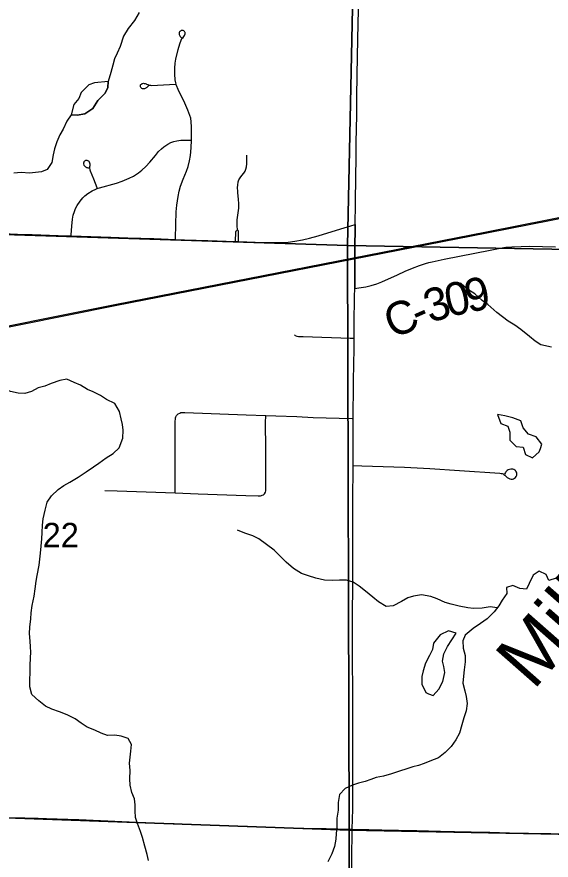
# Model space of a CAD drawing. Extents: x 0 to 34, y 0 to 22.
# Drawn here: x 4.092 to 5.012, y 18.428 to 19.878 of the extents above; entities that cross this region are included whole.
import ezdxf

# ---------------------------------------------------------------- set-up
doc = ezdxf.new("R2010")
doc.units = 0
for name, color, linetype in [('GM_X_County_Road', 7, 'Continuous'), ('GM_X_County_Road_Text', 7, 'Continuous'), ('GM_X_Minor_Lake', 7, 'Continuous'), ('GM_X_Minor_River', 7, 'Continuous'), ('GM_X_Minor_River_Text', 7, 'Continuous'), ('GM_X_Rail_Line', 7, 'Continuous'), ('GM_X_Section', 7, 'Continuous'), ('GM_X_Section_Text', 7, 'Continuous'), ('GM_X_State_Route', 7, 'Continuous'), ('GM_X_Township_Road', 7, 'Continuous')]:
    doc.layers.add(name, color=color, linetype=linetype)

msp = doc.modelspace()

# ---------------------------------------------------------------- linework, layer by layer
at = {"layer": 'GM_X_County_Road'}
for points in [[(4.3666, 19.7624), (4.3659, 19.7649), (4.365, 19.7698), (4.3643, 19.7797), (4.3642, 19.7896), (4.3647, 19.7983), (4.3658, 19.8051), (4.3698, 19.822), (4.3727, 19.8315), (4.3751, 19.8379), (4.3766, 19.8406), (4.3785, 19.8428), (4.3797, 19.8444), (4.3809, 19.8459), (4.3815, 19.8469), (4.3817, 19.8476), (4.382, 19.8485), (4.3821, 19.8494), (4.3821, 19.8501), (4.3819, 19.8512), (4.3817, 19.852), (4.3811, 19.8529), (4.3804, 19.8537), (4.3798, 19.8542), (4.3789, 19.8546), (4.378, 19.8548), (4.3772, 19.8549), (4.3762, 19.8548), (4.3753, 19.8545), (4.3745, 19.854), (4.3738, 19.8535), (4.373, 19.8528), (4.3724, 19.8521), (4.372, 19.8513), (4.3717, 19.8505), (4.3716, 19.8495), (4.3716, 19.8486), (4.3718, 19.8476), (4.3721, 19.8466), (4.3728, 19.8453), (4.3736, 19.8443), (4.3745, 19.8434), (4.3754, 19.8426), (4.3766, 19.8419)], [(4.3199, 19.7606), (4.3194, 19.7599), (4.3186, 19.7589), (4.3177, 19.7581), (4.3168, 19.7573), (4.3161, 19.7566), (4.3152, 19.7559), (4.3144, 19.7554), (4.3135, 19.7549), (4.3122, 19.7544), (4.3112, 19.7542), (4.3102, 19.7542), (4.3093, 19.7542), (4.3084, 19.7545), (4.3076, 19.7548), (4.3067, 19.7554), (4.3061, 19.7559), (4.3056, 19.7567), (4.3052, 19.7575), (4.3051, 19.7584), (4.305, 19.7593), (4.3052, 19.7602), (4.3055, 19.7611), (4.306, 19.7619), (4.3067, 19.7625), (4.3075, 19.763), (4.3083, 19.7634), (4.3093, 19.7637), (4.3104, 19.7638), (4.3116, 19.7637), (4.3134, 19.7634), (4.3147, 19.763), (4.3158, 19.7626), (4.3172, 19.762), (4.3181, 19.7615), (4.319, 19.7612), (4.3208, 19.7607), (4.3222, 19.7604), (4.3244, 19.7603), (4.3655, 19.7624), (4.3666, 19.7624)], [(4.3928, 19.6659), (4.3929, 19.6684), (4.3931, 19.6889), (4.3926, 19.6976), (4.3917, 19.7037), (4.3903, 19.7085), (4.3867, 19.7178), (4.3813, 19.7297), (4.3701, 19.7532), (4.3672, 19.7601), (4.3666, 19.7624)], [(4.2309, 19.5829), (4.2345, 19.5842), (4.2638, 19.5924), (4.2738, 19.5958), (4.2859, 19.6007), (4.293, 19.6044), (4.302, 19.61), (4.3073, 19.6143), (4.3146, 19.621), (4.3214, 19.6283), (4.3308, 19.6399), (4.3364, 19.6465), (4.3412, 19.6514), (4.3451, 19.6545), (4.3523, 19.6592), (4.3573, 19.6618), (4.3626, 19.6637), (4.368, 19.665), (4.3748, 19.6658), (4.3885, 19.6659), (4.3928, 19.6659)], [(4.3656, 19.4954), (4.3656, 19.4969), (4.3662, 19.521), (4.3668, 19.5428), (4.3679, 19.5545), (4.3699, 19.5693), (4.3718, 19.5784), (4.3743, 19.5868), (4.3788, 19.599), (4.3845, 19.6128), (4.3872, 19.621), (4.3896, 19.6307), (4.3912, 19.6399), (4.3923, 19.6529), (4.3928, 19.6659)], [(4.4719, 19.5117), (4.4716, 19.5186), (4.4718, 19.5293), (4.4725, 19.5374), (4.4742, 19.5491), (4.4745, 19.5517), (4.4745, 19.554), (4.4746, 19.5564), (4.4739, 19.5644), (4.4726, 19.5755), (4.4725, 19.5796), (4.4724, 19.5831), (4.4728, 19.5906), (4.473, 19.5925), (4.4734, 19.5944), (4.4739, 19.5962), (4.4746, 19.5981), (4.4754, 19.5995), (4.4766, 19.6015), (4.4798, 19.6054), (4.483, 19.6092), (4.4852, 19.6127), (4.4866, 19.616), (4.4876, 19.6201), (4.4881, 19.6255), (4.4884, 19.6405)], [(4.2309, 19.5829), (4.2305, 19.5841), (4.2247, 19.5988), (4.219, 19.6127), (4.2186, 19.6144), (4.2184, 19.6157), (4.2182, 19.6177), (4.2182, 19.619), (4.2183, 19.6201), (4.2183, 19.6212), (4.2184, 19.6222), (4.2184, 19.6236), (4.2184, 19.625), (4.2181, 19.6268), (4.2173, 19.6285), (4.2167, 19.6293), (4.216, 19.6299), (4.2152, 19.6304), (4.2144, 19.6308), (4.2135, 19.6311), (4.2126, 19.6312), (4.2107, 19.6309), (4.2099, 19.6306), (4.2091, 19.6301), (4.2079, 19.6287), (4.2075, 19.6279), (4.2072, 19.627), (4.2071, 19.6261), (4.2071, 19.6251), (4.2076, 19.6233), (4.2087, 19.6218), (4.2106, 19.6202), (4.2115, 19.6197), (4.2123, 19.6192), (4.2133, 19.6188), (4.2147, 19.6184), (4.2159, 19.6183), (4.2167, 19.6183), (4.2177, 19.6186)], [(4.1861, 19.5015), (4.1862, 19.5031), (4.187, 19.5184), (4.1882, 19.5301), (4.1896, 19.5374), (4.1914, 19.5434), (4.1936, 19.5485), (4.1965, 19.554), (4.2014, 19.5613), (4.206, 19.567), (4.2096, 19.5704), (4.2146, 19.5741), (4.222, 19.5787), (4.2286, 19.5821), (4.2309, 19.5829)], [(3.6774, 19.518), (3.7121, 19.5174), (3.7432, 19.5163), (3.7706, 19.5153), (3.8078, 19.514), (3.8389, 19.513), (3.8656, 19.5119), (3.9264, 19.51), (3.9504, 19.5095), (3.9734, 19.5086), (4.0138, 19.5074), (4.0436, 19.5065), (4.0933, 19.5047), (4.1188, 19.5038), (4.1635, 19.5023), (4.1861, 19.5015)], [(4.4687, 19.492), (4.4738, 19.4919), (4.5027, 19.4908), (4.5257, 19.4902), (4.5462, 19.4902), (4.5592, 19.4909), (4.5708, 19.4922), (4.5842, 19.4947), (4.5963, 19.4975), (4.6112, 19.5018), (4.6501, 19.5134), (4.6672, 19.5187), (4.6746, 19.5209)], [(4.6746, 19.5209), (4.6744, 19.51), (4.6742, 19.4864), (4.674, 19.4417), (4.6738, 19.4111)], [(4.1861, 19.5015), (4.2542, 19.4991), (4.2834, 19.4981), (4.3282, 19.4968), (4.3656, 19.4954)], [(4.4687, 19.492), (4.4687, 19.4928), (4.4692, 19.5073), (4.4695, 19.5089), (4.4699, 19.5098), (4.4705, 19.5106), (4.4719, 19.5117)], [(4.4738, 19.4919), (4.4738, 19.493), (4.474, 19.5063), (4.4739, 19.5078), (4.4736, 19.5094), (4.473, 19.5106), (4.4719, 19.5117)], [(4.3656, 19.4954), (4.381, 19.4948), (4.4208, 19.4937), (4.4687, 19.492)], [(4.6738, 19.4111), (4.6811, 19.4122), (4.6927, 19.414), (4.7023, 19.4161), (4.7118, 19.4189), (4.7203, 19.4225), (4.7475, 19.4347), (4.7606, 19.4406), (4.7732, 19.4458), (4.7855, 19.4505), (4.7956, 19.4538), (4.8014, 19.4555), (4.807, 19.4568), (4.8277, 19.4613), (4.9069, 19.4772), (4.9241, 19.4805), (4.9339, 19.4819), (4.9439, 19.4828), (4.9601, 19.4835), (4.9744, 19.4836), (5.0191, 19.4825)], [(4.671, 19.1066), (4.6859, 19.1062), (4.7592, 19.1038), (4.8033, 19.1013), (4.8542, 19.0979), (4.9238, 19.0934), (4.9258, 19.0932), (4.9274, 19.0927), (4.9291, 19.0921), (4.9302, 19.0914), (4.9323, 19.0899), (4.9335, 19.0887), (4.9349, 19.0873), (4.9363, 19.0862), (4.9383, 19.0847), (4.9406, 19.0836), (4.943, 19.0831), (4.9455, 19.0833), (4.9472, 19.0838), (4.9488, 19.0847), (4.9502, 19.086), (4.9516, 19.088), (4.9526, 19.0902), (4.9529, 19.092), (4.9526, 19.0936), (4.9521, 19.0954), (4.9512, 19.097), (4.9503, 19.098), (4.9494, 19.0987), (4.9478, 19.0996), (4.9461, 19.1002), (4.9445, 19.1005), (4.9424, 19.1004), (4.9403, 19.1001), (4.9381, 19.0993), (4.9363, 19.0981), (4.935, 19.0971), (4.934, 19.0959), (4.933, 19.0945), (4.9313, 19.0916)], [(4.0751, 18.5015), (4.1061, 18.5007), (4.1292, 18.5002), (4.1435, 18.4998), (4.1621, 18.4992), (4.1989, 18.4979), (4.249, 18.4957), (4.2975, 18.4935), (4.3142, 18.4928), (4.3273, 18.4923), (4.3447, 18.4917), (4.3633, 18.491), (4.3826, 18.4902), (4.4667, 18.4872), (4.4895, 18.4865), (4.5329, 18.4851), (4.5684, 18.484), (4.6044, 18.4828), (4.6249, 18.4823), (4.6647, 18.4813), (4.6695, 18.4812)], [(4.6695, 18.4812), (4.6983, 18.4807), (4.7206, 18.4801), (4.7492, 18.4796), (4.7809, 18.4789), (4.8213, 18.4778), (4.8455, 18.4772), (4.8741, 18.4767), (4.9065, 18.476), (4.94, 18.4752), (4.973, 18.4744), (5.0115, 18.4737), (5.0521, 18.4726), (5.0836, 18.4718), (5.1116, 18.4712), (5.1308, 18.4708), (5.1559, 18.4701), (5.1868, 18.4693), (5.2073, 18.4689), (5.2433, 18.4682), (5.2856, 18.4673), (5.297, 18.4671)]]:
    msp.add_lwpolyline(points, dxfattribs=at)
at = {"layer": 'GM_X_Minor_Lake'}
for points in [[(4.1862, 19.7095), (4.1964, 19.7089), (4.2093, 19.7113), (4.2232, 19.7206), (4.2318, 19.7341), (4.2442, 19.7467), (4.2489, 19.7569), (4.2498, 19.7667)], [(4.2498, 19.7667), (4.2259, 19.7645), (4.2164, 19.7613), (4.2032, 19.7483), (4.1992, 19.7377), (4.1903, 19.7273), (4.1862, 19.7095)], [(4.9195, 19.1944), (4.9253, 19.1791), (4.9373, 19.1743), (4.9405, 19.164), (4.941, 19.1503), (4.9514, 19.1391), (4.9635, 19.1381), (4.9675, 19.1255), (4.9799, 19.1196), (4.9914, 19.1304), (4.9933, 19.136)], [(4.9933, 19.136), (4.9959, 19.1436), (4.9859, 19.1559), (4.9727, 19.1603), (4.9634, 19.1715), (4.9595, 19.1837), (4.9459, 19.1889), (4.932, 19.1922), (4.9195, 19.1944)], [(4.8485, 18.8185), (4.835, 18.8226), (4.8208, 18.8156), (4.8095, 18.8011), (4.8074, 18.7905), (4.8023, 18.7803), (4.7956, 18.7668), (4.7915, 18.7536), (4.7895, 18.7438), (4.7892, 18.7305), (4.7961, 18.7163), (4.801, 18.7143)], [(4.801, 18.7143), (4.8086, 18.7111), (4.8186, 18.7223), (4.8257, 18.7351), (4.829, 18.7506), (4.8273, 18.7609), (4.8249, 18.7704), (4.827, 18.7829), (4.8333, 18.7953), (4.8485, 18.8185)]]:
    msp.add_lwpolyline(points, dxfattribs=at)
at = {"layer": 'GM_X_Minor_River'}
for points in [[(4.303, 19.8856), (4.2947, 19.8718), (4.2838, 19.8583), (4.276, 19.8448), (4.2704, 19.8274), (4.2652, 19.8158), (4.2605, 19.806), (4.2576, 19.795), (4.2543, 19.7826), (4.2498, 19.7667), (4.2489, 19.7569), (4.2442, 19.7467), (4.2318, 19.7341), (4.2232, 19.7206), (4.2093, 19.7113), (4.1964, 19.7089), (4.1862, 19.7095), (4.1784, 19.6987), (4.1721, 19.6851), (4.1666, 19.6754), (4.161, 19.6633), (4.157, 19.6509), (4.1549, 19.641), (4.1527, 19.6278), (4.1449, 19.6154), (4.135, 19.6118), (4.1247, 19.6105), (4.1141, 19.6096), (4.1001, 19.6102), (4.0872, 19.6093)], [(5.0127, 19.3102), (4.9942, 19.3144), (4.9845, 19.3206), (4.9744, 19.3284), (4.9595, 19.3405), (4.9494, 19.3479), (4.9381, 19.3546), (4.928, 19.3623), (4.9183, 19.3697), (4.903, 19.3837), (4.8933, 19.3903), (4.8806, 19.4016), (4.8687, 19.4094), (4.856, 19.421)], [(4.2019, 19.2447), (4.191, 19.2494), (4.1782, 19.255), (4.1664, 19.2529), (4.1515, 19.2475), (4.1408, 19.2432), (4.129, 19.24), (4.1175, 19.2338), (4.106, 19.2306), (4.0947, 19.2308), (4.0815, 19.2341), (4.0683, 19.2396), (4.046, 19.2474)], [(4.3188, 18.4276), (4.3168, 18.4376), (4.3129, 18.4524), (4.3086, 18.4673), (4.3054, 18.4776), (4.3, 18.4914), (4.2964, 18.5017), (4.2958, 18.5127), (4.296, 18.5233), (4.2947, 18.5336), (4.2904, 18.5447), (4.2872, 18.5569), (4.287, 18.5679), (4.2877, 18.5823), (4.2864, 18.5949), (4.2874, 18.6055), (4.2883, 18.6153), (4.2897, 18.627), (4.2838, 18.6374), (4.2718, 18.6414), (4.2612, 18.6428), (4.2483, 18.6426), (4.2374, 18.6466), (4.2268, 18.6518), (4.2133, 18.657), (4.2032, 18.6636), (4.1927, 18.671), (4.1788, 18.6778), (4.1656, 18.6833), (4.1525, 18.6877), (4.1416, 18.6929), (4.13, 18.7018), (4.1184, 18.7127), (4.1149, 18.726), (4.1147, 18.7378), (4.1154, 18.7511), (4.1156, 18.7628), (4.1162, 18.7761), (4.1164, 18.7856), (4.1162, 18.7951), (4.1153, 18.8046), (4.1144, 18.8179), (4.1146, 18.8285), (4.1168, 18.8429), (4.1173, 18.8535), (4.1187, 18.866), (4.1221, 18.8819), (4.1242, 18.8944), (4.1256, 18.908), (4.1273, 18.9178), (4.1307, 18.9352), (4.132, 18.9454), (4.1334, 18.956), (4.1343, 18.9682), (4.1353, 18.9807), (4.1359, 18.9917), (4.1366, 19.0042), (4.1379, 19.0152), (4.1412, 19.0299), (4.1449, 19.0439), (4.1519, 19.0544), (4.1635, 19.0655), (4.1731, 19.0722), (4.1835, 19.078), (4.1981, 19.0865), (4.2115, 19.0957), (4.2242, 19.1042), (4.2338, 19.1105), (4.2461, 19.1201), (4.258, 19.1274), (4.2684, 19.1371), (4.2748, 19.1537), (4.2755, 19.1673), (4.2741, 19.1772), (4.272, 19.1871), (4.2689, 19.1993), (4.2608, 19.2132), (4.2469, 19.2203), (4.2364, 19.2273), (4.2236, 19.2332), (4.2139, 19.2372), (4.2019, 19.2447)], [(4.9192, 18.8619), (4.9071, 18.8637), (4.8934, 18.8613), (4.8782, 18.8608), (4.8683, 18.8618), (4.8536, 18.8651), (4.8396, 18.8684), (4.8295, 18.8709), (4.8156, 18.8776), (4.805, 18.8812), (4.7888, 18.8842), (4.7751, 18.8822), (4.7655, 18.8793), (4.7544, 18.8727), (4.7402, 18.8654), (4.7281, 18.8645), (4.715, 18.8723), (4.7049, 18.8801), (4.6922, 18.8906), (4.6817, 18.8995), (4.6712, 18.9062), (4.6596, 18.9098), (4.6478, 18.9093), (4.6364, 18.9091), (4.622, 18.9098), (4.6069, 18.9131), (4.5941, 18.9172), (4.5824, 18.9208), (4.5682, 18.9294), (4.5559, 18.9403), (4.5462, 18.95), (4.5354, 18.9612), (4.5223, 18.9709), (4.5089, 18.9807), (4.4983, 18.9858), (4.4848, 18.9902), (4.4724, 18.9954)], [(4.9913, 18.9251), (4.9809, 18.9184), (4.9742, 18.9041), (4.9694, 18.894), (4.9581, 18.8953), (4.9461, 18.9001), (4.935, 18.8969), (4.9356, 18.8867), (4.9278, 18.8754), (4.9219, 18.8653), (4.9137, 18.8552), (4.9017, 18.8433), (4.8902, 18.8352), (4.8779, 18.8263), (4.8636, 18.8148), (4.86, 18.805), (4.8606, 18.7925), (4.8637, 18.7803), (4.8639, 18.7693), (4.8621, 18.7553), (4.8612, 18.7447), (4.8598, 18.7322), (4.8633, 18.7192), (4.8658, 18.7093), (4.8671, 18.6975), (4.8657, 18.6846), (4.8613, 18.6726), (4.8584, 18.6609), (4.8539, 18.6465), (4.848, 18.6349), (4.8395, 18.6236), (4.8294, 18.6132), (4.8179, 18.604), (4.803, 18.5985), (4.7934, 18.5946), (4.7835, 18.591), (4.774, 18.5885), (4.7633, 18.5853), (4.7511, 18.5813), (4.7373, 18.5767), (4.7232, 18.5724), (4.711, 18.57), (4.7015, 18.5667), (4.6916, 18.5631), (4.6801, 18.5603), (4.6698, 18.5571), (4.6576, 18.5516), (4.6475, 18.5408), (4.6454, 18.5272), (4.6451, 18.5143), (4.6433, 18.5003), (4.643, 18.4851), (4.6421, 18.4742), (4.6411, 18.4643), (4.639, 18.4518), (4.6342, 18.439), (4.6278, 18.4251)], [(5.0206, 18.9131), (5.0077, 18.9092), (5.0033, 18.9191), (4.9913, 18.9251)]]:
    msp.add_lwpolyline(points, dxfattribs=at)
at = {"layer": 'GM_X_Rail_Line'}
for points in [[(2.1, 18.9599), (2.5738, 19.0523), (3.1234, 19.1602), (3.6767, 19.2666), (4.2609, 19.3838), (4.9006, 19.5087), (5.4948, 19.6259), (6.096, 19.7423), (6.7148, 19.8649), (7.2736, 19.9767), (7.8416, 20.0877), (8.2886, 20.1741), (8.3633, 20.1886), (8.9, 20.2933)], [(2.1, 18.9575), (2.5743, 19.05), (3.1238, 19.158), (3.6772, 19.2644), (4.2614, 19.3816), (4.9011, 19.5065), (5.4953, 19.6236), (6.0964, 19.7401), (6.7153, 19.8626), (7.2741, 19.9744), (7.8421, 20.0855), (8.2891, 20.1718), (8.3637, 20.1864), (8.9, 20.2909)]]:
    msp.add_lwpolyline(points, dxfattribs=at)
at = {"layer": 'GM_X_Section'}
for points in [[(3.6779, 20.5235), (4.6829, 20.4926), (4.6614, 19.4847), (3.6762, 19.5163)], [(4.6829, 20.4926), (5.7169, 20.4716), (5.6833, 19.4667), (4.6614, 19.4847)], [(3.6762, 19.5163), (4.6614, 19.4847), (4.6642, 18.4797), (3.6746, 18.5151)], [(4.6614, 19.4847), (5.6833, 19.4667), (5.6535, 18.4609), (4.6642, 18.4797)], [(3.6746, 18.5151), (4.6642, 18.4797), (4.6605, 17.4748), (3.6575, 17.498)], [(4.6642, 18.4797), (5.6535, 18.4609), (5.6551, 17.4555), (4.6605, 17.4748)]]:
    msp.add_lwpolyline(points, close=True, dxfattribs=at)
at = {"layer": 'GM_X_State_Route'}
for points in [[(4.6768, 19.6834), (4.6772, 19.7114), (4.6776, 19.74), (4.6782, 19.7785), (4.6791, 19.8395), (4.6807, 19.9165)], [(4.6754, 19.5617), (4.6763, 19.6387), (4.6765, 19.6642), (4.6768, 19.6834)], [(4.6746, 19.5209), (4.6753, 19.5566), (4.6754, 19.5617)], [(4.6738, 19.4111), (4.674, 19.4417), (4.6742, 19.4864), (4.6744, 19.51), (4.6746, 19.5209)], [(4.673, 19.3413), (4.6731, 19.3503), (4.6737, 19.3975), (4.6738, 19.4111)], [(4.6718, 19.2531), (4.6726, 19.308), (4.6728, 19.3254), (4.673, 19.3413)], [(4.6691, 18.3861), (4.669, 18.4358), (4.6693, 18.4744), (4.6695, 18.4812), (4.6703, 18.516), (4.6707, 18.5533), (4.6705, 18.6372), (4.6704, 18.6826), (4.6703, 18.7174), (4.6702, 18.774), (4.6702, 18.7988), (4.6702, 18.8374), (4.6702, 18.8604), (4.6706, 18.8908), (4.6705, 18.9188), (4.6705, 18.9418), (4.6704, 18.971), (4.6706, 19.0077), (4.6705, 19.045), (4.671, 19.1066), (4.671, 19.126), (4.6709, 19.1321), (4.6713, 19.1575), (4.6714, 19.1877), (4.6717, 19.2471), (4.6718, 19.2531)]]:
    msp.add_lwpolyline(points, dxfattribs=at)
at = {"layer": 'GM_X_Township_Road'}
for points in [[(4.5703, 19.3315), (4.5716, 19.3304), (4.5742, 19.3292), (4.5769, 19.3287), (4.5851, 19.3285), (4.6659, 19.3256), (4.6728, 19.3254)], [(4.3703, 19.1954), (4.373, 19.1969), (4.3749, 19.1976), (4.3783, 19.198), (4.3817, 19.198), (4.4872, 19.194), (4.5208, 19.1927)], [(4.365, 19.0596), (4.365, 19.0623), (4.3651, 19.0882), (4.3648, 19.1311), (4.3648, 19.1571), (4.3651, 19.1835), (4.3652, 19.1858), (4.3655, 19.1884), (4.366, 19.1906), (4.3669, 19.1924), (4.3681, 19.1937), (4.3703, 19.1954)], [(4.5188, 19.0579), (4.5202, 19.0607), (4.5207, 19.0631), (4.521, 19.066), (4.5209, 19.0679), (4.5208, 19.0716), (4.5207, 19.1013), (4.5206, 19.1358), (4.5204, 19.18), (4.5208, 19.1927)], [(4.5208, 19.1927), (4.5381, 19.1921), (4.5741, 19.1907), (4.6026, 19.1893), (4.6694, 19.1876), (4.6714, 19.1877)], [(4.2441, 19.064), (4.2649, 19.0632), (4.365, 19.0596)], [(4.365, 19.0596), (4.4045, 19.0581), (4.4864, 19.0554), (4.5075, 19.0548), (4.5094, 19.0547), (4.5116, 19.0547), (4.5133, 19.0551), (4.5148, 19.0556), (4.5167, 19.0565), (4.5188, 19.0579)]]:
    msp.add_lwpolyline(points, dxfattribs=at)

# ---------------------------------------------------------------- texts
at = {"layer": 'GM_X_County_Road_Text'}
for s, rotation, p in [('9', 12.1405, (4.8695, 19.3691)), ('3', 17.9384, (4.8035, 19.3513)), ('0', 12.2443, (4.8353, 19.3617)), ('C', 22.0283, (4.7386, 19.3242)), ('-', 23.7453, (4.7835, 19.3424))]:
    msp.add_text(s, height=0.0568, rotation=rotation, dxfattribs=at).set_placement(p)
at = {"layer": 'GM_X_Minor_River_Text'}
msp.add_text('Miller', height=0.09477, rotation=48.7053, dxfattribs=at).set_placement((4.9812, 18.7189))
at = {"layer": 'GM_X_Section_Text'}
msp.add_text('22', height=0.04186, rotation=0, dxfattribs=at).set_placement((4.1369, 18.9662))

doc.saveas('drawing.dxf')
